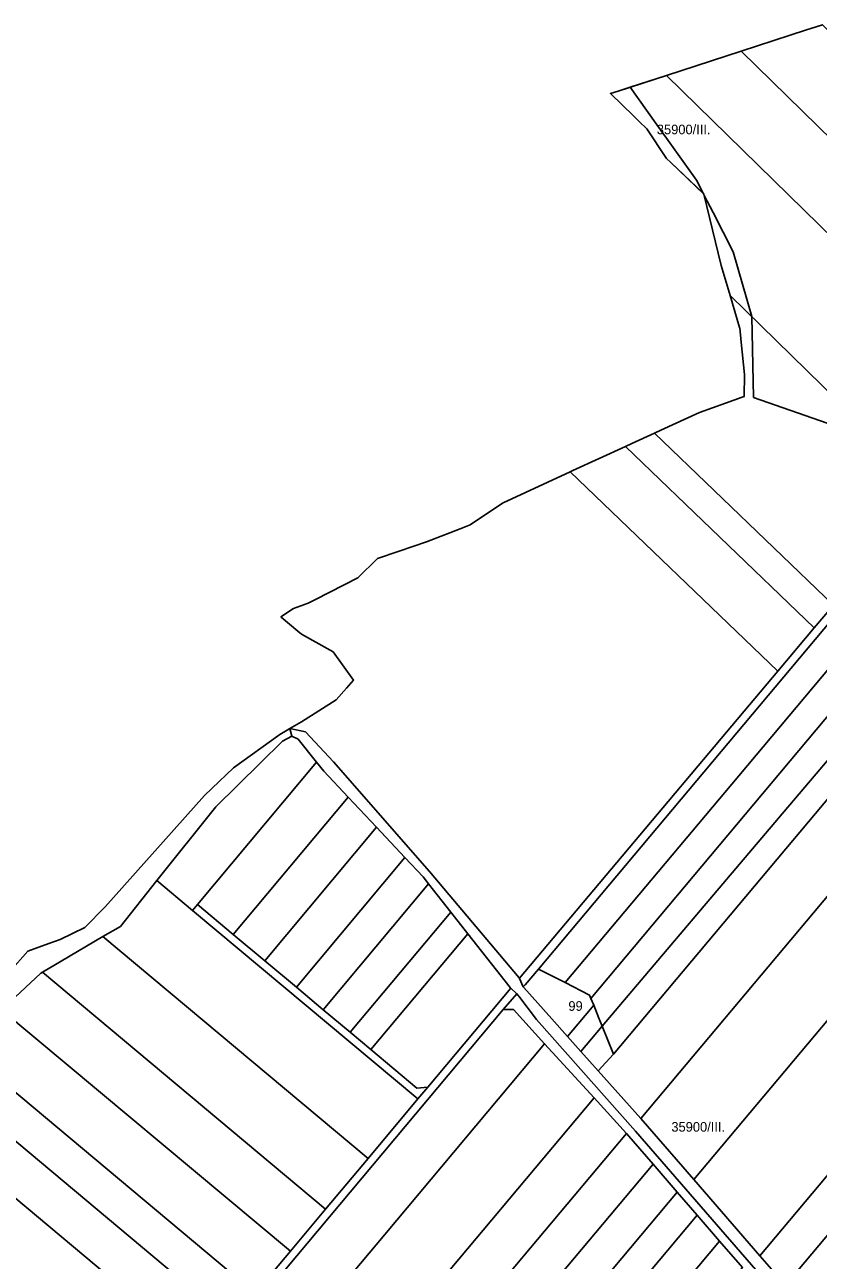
# Model space of a CAD drawing. Extents: x -545779 to -541342, y -1153413 to -1149956.
# Drawn here: x -543965 to -543553, y -1150751 to -1150109 of the extents above; entities that cross this region are included whole.
import ezdxf

# ---------------------------------------------------------------- set-up
doc = ezdxf.new("R2010")
doc.units = 0
for name, color, linetype in [('95560013', 7, 'Continuous'), ('95610013', 7, 'Continuous'), ('95620013', 7, 'Continuous'), ('95630013', 7, 'Continuous'), ('95640013', 7, 'Continuous'), ('95660013', 7, 'Continuous')]:
    doc.layers.add(name, color=color, linetype=linetype)

msp = doc.modelspace()

# ---------------------------------------------------------------- linework, layer by layer
at = {"layer": '95560013'}
for points in [[(-543559.47, -1150112.01), (-543557.16, -1150111.26), (-543551.17, -1150109.31), (-543409.03, -1150248.44), (-543434.46, -1150278.68), (-543513.95, -1150200.87), (-543593.45, -1150123.06)], [(-543457.76, -1150306.4), (-543544.98, -1150221.03), (-543632.2, -1150135.66), (-543593.45, -1150123.06), (-543513.95, -1150200.87), (-543434.46, -1150278.68)], [(-543632.15, -1150178.74), (-543642.4, -1150163.35), (-543646.33, -1150159.54), (-543649.29, -1150156.67), (-543661.23, -1150145.1), (-543657.21, -1150143.79), (-543632.2, -1150135.66), (-543544.98, -1150221.03), (-543457.76, -1150306.4), (-543495.52, -1150351.31), (-543599.11, -1150249.93), (-543603.71, -1150234.39), (-543612.7, -1150197.25), (-543629.86, -1150180.92)], [(-543594.13, -1150266.72), (-543594.19, -1150266.51), (-543599.11, -1150249.93), (-543495.52, -1150351.31), (-543545.5, -1150410.75), (-543638.38, -1150321.45), (-543635.09, -1150319.94), (-543614.97, -1150310.74), (-543601.55, -1150305.9), (-543592.79, -1150302.75), (-543591.79, -1150302.39), (-543591.7, -1150290.93), (-543593.39, -1150274.14)], [(-543653.5, -1150328.38), (-543650.2, -1150326.86), (-543638.38, -1150321.45), (-543545.5, -1150410.75), (-543555.49, -1150422.63)], [(-543682.13, -1150341.56), (-543680.78, -1150340.94), (-543653.5, -1150328.38), (-543555.49, -1150422.63), (-543574.41, -1150445.14)], [(-543821.63, -1150425.96), (-543823.65, -1150424.26), (-543832.16, -1150417.11), (-543832.38, -1150416.93), (-543825.83, -1150412.53), (-543818.18, -1150409.77), (-543814.34, -1150407.8), (-543792.47, -1150396.57), (-543782.14, -1150386.64), (-543771.03, -1150382.82), (-543756.74, -1150377.92), (-543739.24, -1150371.12), (-543734.1, -1150369.12), (-543725.01, -1150363.01), (-543716.97, -1150357.6), (-543682.13, -1150341.56), (-543574.41, -1150445.14), (-543708.43, -1150604.56), (-543708.56, -1150604.72), (-543708.68, -1150604.37), (-543755.13, -1150549.13), (-543805.09, -1150492.17), (-543819.62, -1150476.53), (-543827.7, -1150474.93), (-543822.81, -1150472.07), (-543821.65, -1150471.39), (-543803.6, -1150459.91), (-543798.35, -1150453.88), (-543794.72, -1150449.7), (-543805.24, -1150435.1)], [(-543698.58, -1150599.85), (-543608.24, -1150492.17), (-543517.92, -1150384.52), (-543512.47, -1150384.23), (-543504.42, -1150392.01), (-543594.6, -1150499.49), (-543684.71, -1150606.9)], [(-543594.6, -1150499.49), (-543504.42, -1150392.01), (-543493.28, -1150402.76), (-543582.34, -1150508.9), (-543671.39, -1150615.05), (-543672.09, -1150613.32), (-543684.71, -1150606.9)], [(-543582.34, -1150508.9), (-543493.28, -1150402.76), (-543482.32, -1150413.34), (-543573.95, -1150521.4), (-543665.6, -1150629.43), (-543667.22, -1150625.41), (-543669.94, -1150618.67), (-543671.39, -1150615.05)], [(-543566.52, -1150533.05), (-543659.69, -1150644.11), (-543665.6, -1150629.43), (-543573.95, -1150521.4), (-543482.32, -1150413.34), (-543473.34, -1150421.99)], [(-543645.51, -1150677.5), (-543667.56, -1150652.71), (-543659.69, -1150644.11), (-543566.52, -1150533.05), (-543473.34, -1150421.99), (-543450.02, -1150444.5), (-543547.76, -1150560.98)], [(-543519, -1150591.3), (-543617.92, -1150709.21), (-543645.51, -1150677.5), (-543547.76, -1150560.98), (-543450.02, -1150444.5), (-543420.07, -1150473.4)], [(-543583.61, -1150748.73), (-543617.92, -1150709.21), (-543519, -1150591.3), (-543420.07, -1150473.4), (-543382.79, -1150509.37), (-543483.2, -1150629.05)], [(-543823.43, -1150480.51), (-543813.81, -1150492.41), (-543875.68, -1150566.32), (-543878.25, -1150569.39), (-543896.75, -1150553.9), (-543866.15, -1150515.56), (-543831.59, -1150481.42), (-543826.77, -1150478.79)], [(-543857.18, -1150581.81), (-543875.68, -1150566.32), (-543813.81, -1150492.41), (-543810.09, -1150497.01), (-543797.48, -1150510.48)], [(-543797.48, -1150510.48), (-543782.74, -1150526.2), (-543840.78, -1150595.54), (-543857.18, -1150581.81)], [(-543469.3, -1150643.72), (-543570.28, -1150764.08), (-543583.61, -1150748.73), (-543483.2, -1150629.05), (-543382.79, -1150509.37), (-543368.31, -1150523.35)], [(-543368.31, -1150523.35), (-543355.89, -1150535.34), (-543457.4, -1150656.33), (-543558.9, -1150777.31), (-543570.28, -1150764.08), (-543469.3, -1150643.72)], [(-543824.34, -1150609.3), (-543840.78, -1150595.54), (-543782.74, -1150526.2), (-543767.97, -1150541.96)], [(-543767.97, -1150541.96), (-543758.57, -1150552), (-543755.72, -1150555.62), (-543810.41, -1150620.96), (-543824.34, -1150609.3)], [(-543787.12, -1150698.24), (-543924.79, -1150583.01), (-543915.73, -1150577.68), (-543896.75, -1150553.9), (-543878.25, -1150569.39), (-543761.24, -1150667.33)], [(-543810.41, -1150620.96), (-543755.72, -1150555.62), (-543744.15, -1150570.29), (-543796.39, -1150632.69)], [(-543735.34, -1150581.48), (-543785.7, -1150641.64), (-543796.39, -1150632.69), (-543744.15, -1150570.29)], [(-543946.44, -1150595.74), (-543924.79, -1150583.01), (-543787.12, -1150698.24), (-543809.16, -1150724.58), (-543956.21, -1150601.49)], [(-543977.39, -1150620.95), (-543972.94, -1150616.8), (-543957.08, -1150602), (-543956.21, -1150601.49), (-543809.16, -1150724.58), (-543827.47, -1150746.45)], [(-543827.47, -1150746.45), (-543845.7, -1150768.23), (-543993.28, -1150644.7), (-543977.98, -1150621.5), (-543977.39, -1150620.95)], [(-543801.78, -1150722.14), (-543716.9, -1150620.9), (-543711.61, -1150620.82), (-543695.42, -1150638.6), (-543778.48, -1150737.68), (-543861.53, -1150836.77), (-543865.01, -1150840.92), (-543870.95, -1150836.1), (-543886.65, -1150823.39)], [(-543749.03, -1150761.28), (-543828.26, -1150855.81), (-543852.23, -1150838.93), (-543859.01, -1150838.76), (-543861.53, -1150836.77), (-543778.48, -1150737.68), (-543695.42, -1150638.6), (-543669.78, -1150666.75)], [(-543858.13, -1150783.08), (-544004.01, -1150660.97), (-543993.28, -1150644.7), (-543845.7, -1150768.23)], [(-544020.45, -1150676.94), (-544018.78, -1150671.48), (-544015.88, -1150665.87), (-544009.5, -1150669.31), (-544004.01, -1150660.97), (-543858.13, -1150783.08), (-543872.76, -1150800.56)], [(-543817.68, -1150863.26), (-543819.79, -1150861.77), (-543828.26, -1150855.81), (-543749.03, -1150761.28), (-543669.78, -1150666.75), (-543652.94, -1150685.25), (-543729.87, -1150777.02), (-543806.8, -1150868.8)], [(-543980.18, -1150755.91), (-543984.63, -1150753.63), (-544024.7, -1150733.15), (-544026.25, -1150733.04), (-544026.37, -1150732.2), (-544027.19, -1150726.47), (-544028.18, -1150725.94), (-544028.6, -1150725.71), (-544029.66, -1150713.36), (-544030.04, -1150708.97), (-544030.08, -1150708.47), (-544020.45, -1150676.94), (-543872.76, -1150800.56), (-543889.76, -1150820.87), (-543912.05, -1150802.81)], [(-543639.09, -1150701.19), (-543713.46, -1150789.91), (-543787.73, -1150878.52), (-543802.3, -1150871.09), (-543806.8, -1150868.8), (-543729.87, -1150777.02), (-543652.94, -1150685.25)], [(-543626.57, -1150715.69), (-543698.51, -1150801.5), (-543770.45, -1150887.32), (-543787.73, -1150878.52), (-543713.46, -1150789.91), (-543639.09, -1150701.19)], [(-543770.45, -1150887.32), (-543698.51, -1150801.5), (-543626.57, -1150715.69), (-543616.26, -1150727.64), (-543686.23, -1150811.11), (-543756.2, -1150894.58)], [(-543740.79, -1150903.51), (-543746.15, -1150899.7), (-543756.2, -1150894.58), (-543686.23, -1150811.11), (-543616.26, -1150727.64), (-543604.66, -1150741.11), (-543672.72, -1150822.31)], [(-543672.72, -1150822.31), (-543604.66, -1150741.11), (-543592.73, -1150754.92), (-543659.4, -1150834.46), (-543726.08, -1150914), (-543740.79, -1150903.51)]]:
    msp.add_lwpolyline(points, close=True, dxfattribs=at)
at = {"layer": '95610013'}
msp.add_lwpolyline([(-543735.34, -1150581.48), (-543713.28, -1150609.47), (-543713.01, -1150609.72), (-543756.11, -1150661.2), (-543761.74, -1150661.7), (-543785.7, -1150641.64)], close=True, dxfattribs=at)
at = {"layer": '95620013'}
for points in [[(-543671.64, -1150620.7), (-543683.54, -1150634.82), (-543691.64, -1150625.75), (-543706.29, -1150609.34), (-543706.49, -1150609.12), (-543705.55, -1150608.02), (-543698.58, -1150599.85), (-543684.71, -1150606.9), (-543672.09, -1150613.32), (-543671.39, -1150615.05), (-543669.94, -1150618.67)], [(-543676.59, -1150642.6), (-543683.54, -1150634.82), (-543671.64, -1150620.7), (-543669.94, -1150618.67), (-543667.22, -1150625.41), (-543665.6, -1150629.43)], [(-543676.59, -1150642.6), (-543665.6, -1150629.43), (-543659.69, -1150644.11), (-543667.56, -1150652.71)]]:
    msp.add_lwpolyline(points, close=True, dxfattribs=at)
at = {"layer": '95630013'}
for points in [[(-543991.41, -1150621.76), (-543963.72, -1150590.5), (-543952.94, -1150586.62), (-543947, -1150584.48), (-543934.25, -1150578.3), (-543923.67, -1150567.56), (-543872, -1150509.63), (-543868.21, -1150506.03), (-543856.96, -1150495.34), (-543832.89, -1150477.96), (-543829.16, -1150475.78), (-543827.7, -1150474.93), (-543826.77, -1150478.79), (-543831.59, -1150481.42), (-543866.15, -1150515.56), (-543896.75, -1150553.9), (-543915.73, -1150577.68), (-543924.79, -1150583.01), (-543946.44, -1150595.74), (-543956.21, -1150601.49), (-543957.08, -1150602), (-543972.94, -1150616.8)], [(-543561.88, -1150783.67), (-543648.32, -1150684.08), (-543699.66, -1150626.08), (-543708.87, -1150613.91), (-543709.16, -1150613.52), (-543709.83, -1150612.64), (-543713.01, -1150609.72), (-543713.28, -1150609.47), (-543735.34, -1150581.48), (-543744.15, -1150570.29), (-543755.72, -1150555.62), (-543758.57, -1150552), (-543767.97, -1150541.96), (-543782.74, -1150526.2), (-543797.48, -1150510.48), (-543810.09, -1150497.01), (-543813.81, -1150492.41), (-543823.43, -1150480.51), (-543826.77, -1150478.79), (-543827.7, -1150474.93), (-543819.62, -1150476.53), (-543805.09, -1150492.17), (-543755.13, -1150549.13), (-543708.68, -1150604.37), (-543708.56, -1150604.72), (-543706.49, -1150609.12), (-543706.29, -1150609.34), (-543691.64, -1150625.75), (-543683.54, -1150634.82), (-543676.59, -1150642.6), (-543667.56, -1150652.71), (-543645.51, -1150677.5), (-543617.92, -1150709.21), (-543583.61, -1150748.73), (-543570.28, -1150764.08)]]:
    msp.add_lwpolyline(points, dxfattribs=at)
at = {"layer": '95640013'}
for points in [[(-543708.43, -1150604.56), (-543574.41, -1150445.14), (-543555.49, -1150422.63), (-543545.5, -1150410.75), (-543495.52, -1150351.31), (-543457.76, -1150306.4), (-543434.46, -1150278.68), (-543409.03, -1150248.44), (-543389.56, -1150225.27), (-543376.25, -1150209.44), (-543365.4, -1150196.53), (-543354.66, -1150183.76), (-543351.82, -1150186.6), (-543432.3, -1150282.49), (-543512.77, -1150378.38), (-543517.92, -1150384.52), (-543608.24, -1150492.17), (-543698.58, -1150599.85), (-543705.55, -1150608.02), (-543706.49, -1150609.12), (-543708.56, -1150604.72)], [(-543761.24, -1150667.33), (-543878.25, -1150569.39), (-543875.68, -1150566.32), (-543857.18, -1150581.81), (-543840.78, -1150595.54), (-543824.34, -1150609.3), (-543810.41, -1150620.96), (-543796.39, -1150632.69), (-543785.7, -1150641.64), (-543761.74, -1150661.7), (-543756.11, -1150661.2)], [(-543756.11, -1150661.2), (-543713.01, -1150609.72), (-543709.83, -1150612.64), (-543716.9, -1150620.9), (-543801.78, -1150722.14), (-543886.65, -1150823.39), (-543889.76, -1150820.87), (-543872.76, -1150800.56), (-543858.13, -1150783.08), (-543845.7, -1150768.23), (-543827.47, -1150746.45), (-543809.16, -1150724.58), (-543787.12, -1150698.24), (-543761.24, -1150667.33)]]:
    msp.add_lwpolyline(points, close=True, dxfattribs=at)
msp.add_lwpolyline([(-543592.73, -1150754.92), (-543604.66, -1150741.11), (-543616.26, -1150727.64), (-543626.57, -1150715.69), (-543639.09, -1150701.19), (-543652.94, -1150685.25), (-543669.78, -1150666.75), (-543695.42, -1150638.6), (-543711.61, -1150620.82), (-543716.9, -1150620.9), (-543709.83, -1150612.64), (-543709.16, -1150613.52), (-543708.87, -1150613.91), (-543699.66, -1150626.08), (-543648.32, -1150684.08), (-543561.88, -1150783.67)], dxfattribs=at)
at = {"layer": '95660013'}
for points in [[(-543548.675, -1150316.323), (-543586.954, -1150302.925), (-543587.91, -1150260.818), (-543597.48, -1150227.324), (-543607.971, -1150206.868), (-543612.517, -1150198.002), (-543612.7, -1150197.25), (-543613.1, -1150196.87), (-543616.621, -1150190.002), (-543633.018, -1150167.047), (-543633.107, -1150166.92), (-543651.057, -1150141.79), (-543632.2, -1150135.66), (-543593.45, -1150123.06), (-543559.47, -1150112.01), (-543557.16, -1150111.26), (-543551.17, -1150109.31)], [(-543991.41, -1150621.76), (-543963.72, -1150590.5), (-543952.94, -1150586.62), (-543947, -1150584.48), (-543934.25, -1150578.3), (-543923.67, -1150567.56), (-543872, -1150509.63), (-543868.21, -1150506.03), (-543856.96, -1150495.34), (-543832.89, -1150477.96), (-543829.16, -1150475.78), (-543827.7, -1150474.93), (-543822.81, -1150472.07), (-543821.65, -1150471.39), (-543803.6, -1150459.91), (-543798.35, -1150453.88), (-543794.72, -1150449.7), (-543805.24, -1150435.1), (-543821.63, -1150425.96), (-543823.65, -1150424.26), (-543832.16, -1150417.11), (-543832.38, -1150416.93), (-543825.83, -1150412.53), (-543818.18, -1150409.77), (-543814.34, -1150407.8), (-543792.47, -1150396.57), (-543782.14, -1150386.64), (-543771.03, -1150382.82), (-543756.74, -1150377.92), (-543739.24, -1150371.12), (-543734.1, -1150369.12), (-543725.01, -1150363.01), (-543716.97, -1150357.6), (-543682.13, -1150341.56), (-543680.78, -1150340.94), (-543653.5, -1150328.38), (-543650.2, -1150326.86), (-543638.38, -1150321.45), (-543635.09, -1150319.94), (-543614.97, -1150310.74), (-543601.55, -1150305.9), (-543592.79, -1150302.75), (-543591.79, -1150302.39), (-543591.7, -1150290.93), (-543593.39, -1150274.14), (-543594.13, -1150266.72), (-543594.19, -1150266.51), (-543599.11, -1150249.93), (-543603.71, -1150234.39), (-543612.516, -1150198.005), (-543607.971, -1150206.868), (-543597.48, -1150227.324), (-543587.91, -1150260.818), (-543586.954, -1150302.925), (-543548.675, -1150316.323)]]:
    msp.add_lwpolyline(points, dxfattribs=at)
for points in [[(-543657.21, -1150143.79), (-543651.057, -1150141.79), (-543633.107, -1150166.92), (-543633.018, -1150167.047), (-543616.621, -1150190.002), (-543613.1, -1150196.87), (-543629.86, -1150180.92), (-543632.15, -1150178.74), (-543642.4, -1150163.35), (-543646.33, -1150159.54), (-543649.29, -1150156.67), (-543661.23, -1150145.1)], [(-543676.59, -1150642.6), (-543667.56, -1150652.71), (-543659.69, -1150644.11), (-543665.6, -1150629.43), (-543667.22, -1150625.41), (-543669.94, -1150618.67), (-543671.39, -1150615.05), (-543672.09, -1150613.32), (-543684.71, -1150606.9), (-543698.58, -1150599.85), (-543705.55, -1150608.02), (-543706.49, -1150609.12), (-543706.29, -1150609.34), (-543691.64, -1150625.75), (-543683.54, -1150634.82)], [(-543667.56, -1150652.71), (-543676.59, -1150642.6), (-543683.54, -1150634.82), (-543691.64, -1150625.75), (-543706.29, -1150609.34), (-543706.49, -1150609.12), (-543705.55, -1150608.02), (-543698.58, -1150599.85), (-543684.71, -1150606.9), (-543672.09, -1150613.32), (-543671.39, -1150615.05), (-543669.94, -1150618.67), (-543667.22, -1150625.41), (-543665.6, -1150629.43), (-543659.69, -1150644.11)]]:
    msp.add_lwpolyline(points, close=True, dxfattribs=at)

# ---------------------------------------------------------------- texts
for s, p in [('35900/III.', (-543637.165, -1150166.224)), ('99', (-543683.09, -1150621.524)), ('35900/III.', (-543629.616, -1150684.316))]:
    msp.add_text(s, height=5, rotation=0, dxfattribs=at).set_placement(p)

doc.saveas('drawing.dxf')
